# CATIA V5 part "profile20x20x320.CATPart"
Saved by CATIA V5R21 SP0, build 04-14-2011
Part number: profile 20x20x320
Bounding box of the stored display mesh (mm): x -24.289 to -4.289, y -1.335 to 18.665, z 0 to 320
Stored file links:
  C:\Users\2027.DESARCY-LEMIE30\Desktop\Assemblage26.05\profile20x20x320.CATPart
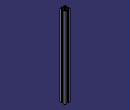
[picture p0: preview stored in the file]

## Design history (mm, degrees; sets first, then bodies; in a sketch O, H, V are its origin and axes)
Body1 (main body)
  Sketch1 on xy-plane, origin (0, 0, 0), H (1, 0, 0), V (0, 1, 0)
    point P1 (-17.2892, 11.6647)
    line L1 (-16.2892, 11.6647) -> (-12.2892, 11.6647)
    point P2 (-11.2892, 11.6647)
    line L2 (-11.2892, 10.6647) -> (-11.2892, 6.6647)
    point P3 (-11.2892, 5.6647)
    line L3 (-12.2892, 5.6647) -> (-16.2892, 5.6647)
    point P4 (-17.2892, 5.6647)
    line L4 (-17.2892, 6.6647) -> (-17.2892, 10.6647)
    point P5 (-24.2892, 18.6647)
    point P6 (-4.2892, 18.6647)
    point P7 (-4.2892, -1.3353)
    line L5 (-11.1892, 18.6647) -> (-11.1892, 16.6647)
    point P8 (-11.1892, 18.6647)
    point P10 (-11.1892, 18.6647)
    point P11 (-17.3892, 18.6647)
    line L6 (-17.3892, 18.6647) -> (-17.3892, 16.6647)
    point P12 (-17.3892, 18.6647)
    line L7 (-11.1892, 18.6647) -> (-4.2892, 18.6647)
    point P14 (-11.1892, 18.6647)
    point P15 (-4.2892, 18.6647)
    point P16 (-11.1892, -1.3353)
    point P17 (-17.3892, -1.3353)
    line L8 (-17.3892, -1.3353) -> (-17.3892, 0.6647)
    point P18 (-17.3892, -1.3353)
    line L9 (-11.1892, -1.3353) -> (-11.1892, 0.6647)
    point P20 (-11.1892, -1.3353)
    line L10 (-24.2892, -1.3353) -> (-17.3892, -1.3353)
    point P22 (-24.2892, -1.3353)
    point P23 (-17.3892, -1.3353)
    line L11 (-11.1892, -1.3353) -> (-4.2892, -1.3353)
    point P24 (-11.1892, -1.3353)
    point P25 (-4.2892, -1.3353)
    line L12 (-24.2892, 18.6647) -> (-17.3892, 18.6647)
    point P26 (-24.2892, 18.6647)
    point P27 (-17.3892, 18.6647)
    point P28 (-4.2892, 5.5647)
    point P29 (-4.2892, 11.7647)
    line L13 (-6.2892, 11.7647) -> (-4.2892, 11.7647)
    point P31 (-4.2892, 11.7647)
    line L14 (-4.2892, 5.5647) -> (-6.2892, 5.5647)
    point P32 (-4.2892, 5.5647)
    point P34 (-24.2892, 5.5647)
    point P35 (-24.2892, 11.7647)
    line L15 (-24.2892, 11.7647) -> (-22.2892, 11.7647)
    point P36 (-24.2892, 11.7647)
    line L16 (-24.2892, 5.5647) -> (-22.2892, 5.5647)
    point P38 (-24.2892, 5.5647)
    line L17 (-4.2892, 18.6647) -> (-4.2892, 11.7647)
    point P40 (-4.2892, 18.6647)
    point P41 (-4.2892, 11.7647)
    line L18 (-24.2892, 18.6647) -> (-24.2892, 11.7647)
    point P42 (-24.2892, 18.6647)
    point P43 (-24.2892, 11.7647)
    line L19 (-24.2892, -1.3353) -> (-24.2892, 5.5647)
    point P44 (-24.2892, -1.3353)
    point P45 (-24.2892, 5.5647)
    line L20 (-4.2892, -1.3353) -> (-4.2892, 5.5647)
    point P46 (-4.2892, -1.3353)
    point P47 (-4.2892, 5.5647)
    line L21 (-22.2892, 5.5647) -> (-22.2892, 1.6647)
    line L22 (-21.2892, 0.6647) -> (-17.3892, 0.6647)
    line L23 (-6.2892, 5.5647) -> (-6.2892, 1.6647)
    line L24 (-11.1892, 0.6647) -> (-7.2892, 0.6647)
    line L25 (-11.1892, 16.6647) -> (-7.2892, 16.6647)
    line L26 (-6.2892, 15.6647) -> (-6.2892, 11.7647)
    line L27 (-17.3892, 16.6647) -> (-21.2892, 16.6647)
    line L28 (-22.2892, 15.6647) -> (-22.2892, 11.7647)
    point P48 (-16.2892, 11.6647)
    point P49 (-17.2892, 10.6647)
    point P50 (-17.2892, 6.6647)
    point P52 (-11.2892, 6.6647)
    point P53 (-11.2892, 10.6647)
    point P54 (-12.2892, 11.6647)
    point P55 (-12.2892, 5.6647)
    line L29 (-16.2892, 11.6647) -> (-21.2892, 16.6647)
    line L30 (-17.2892, 10.6647) -> (-22.2892, 15.6647)
    line L31 (-12.2892, 11.6647) -> (-7.2892, 16.6647)
    line L32 (-16.2892, 5.6647) -> (-21.2892, 0.6647)
    line L33 (-17.2892, 6.6647) -> (-22.2892, 1.6647)
    line L34 (-12.2892, 5.6647) -> (-7.2892, 0.6647)
    line L35 (-11.2892, 6.6647) -> (-6.2892, 1.6647)
    line L36 (-11.2892, 10.6647) -> (-6.2892, 15.6647)
    length L5 = 2
    distance P10 P6 = 6.9
    length L6 = 2
    length L8 = 2
    length L9 = 2
    distance P7 P28 = 6.9
    distance P6 P29 = 6.9
    length L13 = 2
    length L14 = 2
    length L15 = 2
    distance P5 P42 = 0
    length L11 = 6.9
    distance P46 P7 = 0
    distance P1 P48 = 1
    distance P49 P1 = 1
    distance P4 P50 = 1
    distance P54 P2 = 1
    distance P2 P3 = 6
    distance P1 P2 = 6
    horizontal: L1 H, L3 H, L7 H, L10 H, L11 H, L12 H, L13 H, L14 H, L15 H, L16 H, L22 H, L24 H, L25 H, L27 H
    vertical: L2 V, L4 V, L5 V, L6 V, L8 V, L9 V, L17 V, L18 V, L19 V, L20 V, L21 V, L23 V, L26 V, L28 V
    coincidence: P10 P8, P11 P12, P6 P15, P8 P14, P16 L5, P17 L6, P17 P18, P16 P20, P23 L8, P24 L9, P20 P24, P27 L6, P5 P26, P29 P31, P28 P32, P34 L14, P35 L13, P34 P38, P35 P36, P40 L7, P41 L13, P6 P40, P42 L7, P43 L13, P44 L11, P45 L14, P38 P45, P46 L11, P47 L14, P49 L4, P50 L4, P52 L2, P53 L2, P55 L3, P22 P44, P25 P46
    fix: P34, P12, P5, P36, P55
  Pad1: profile Sketch1, direction (0, 0, 1), length 320
  Sketch2 on end face of Pad1, origin (0, 0, 320), H (1, 0, 0), V (0, 1, 0)
    circle A1 centre (-14.2892, 8.6647) radius 2.5
    point P1 (-14.2892, 8.6647)
    reference projected line E1 (-12.2892, 11.6647) -> (-16.2892, 11.6647) from edge [face of Pad1 from Sketch1.L1 | end face of Pad1]
    reference projected line E2 (-11.2892, 6.6647) -> (-11.2892, 10.6647) from edge [face of Pad1 from Sketch1.L2 | end face of Pad1]
    radius A1 = 2.5
    distance P1 E1 = 3
    distance P1 E2 = 3
  Pocket1: profile Sketch2, direction (0, 0, -1), length 320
